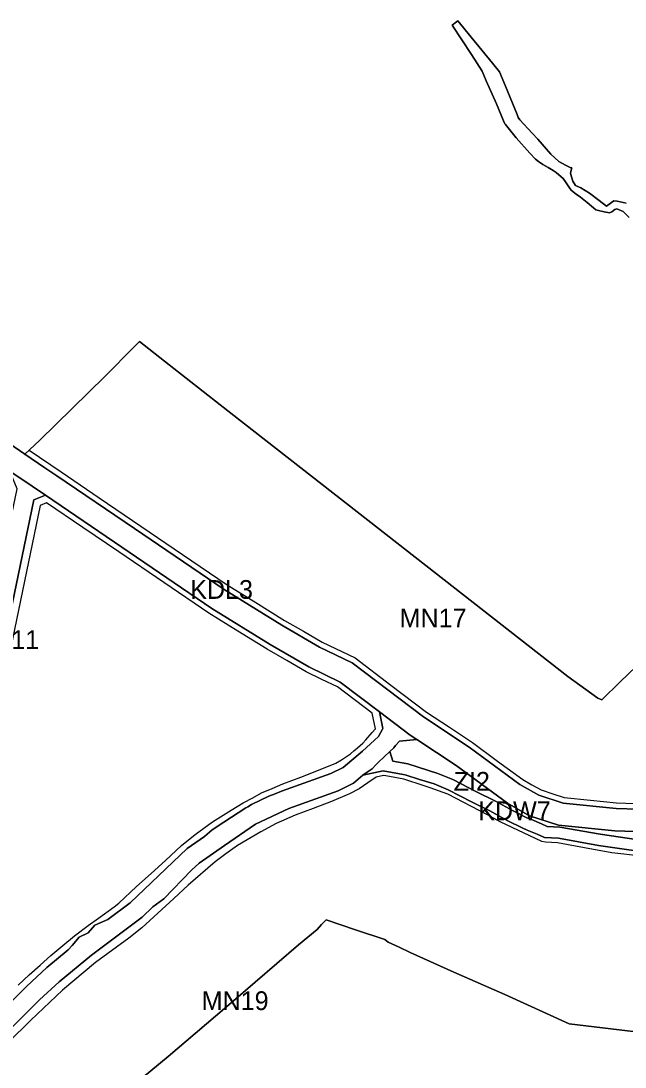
# Model space of a CAD drawing. Extents: x 7439486 to 7443435, y 5551288 to 5554556.
# Drawn here: x 7440135 to 7440457, y 5552234 to 5552792 of the extents above; entities that cross this region are included whole.
import ezdxf

# ---------------------------------------------------------------- set-up
doc = ezdxf.new("R2010")
doc.units = 0
for name, color, linetype in [('linie_rozgraniczajace', 7, 'Continuous'), ('linie_zabudowy_nieprzekraczalne', 7, 'Continuous'), ('oznaczenia_przeznaczen', 7, 'Continuous')]:
    doc.layers.add(name, color=color, linetype=linetype)

msp = doc.modelspace()

# ---------------------------------------------------------------- linework, layer by layer
at = {"layer": 'linie_rozgraniczajace'}
for points in [[(7440386.06, 5552769.12), (7440374.68, 5552782.97), (7440367.62, 5552791.7), (7440366.85, 5552791.14), (7440364.58, 5552789.48), (7440374.9, 5552773.74), (7440380.49, 5552764.99), (7440382.63, 5552759.83), (7440388.1, 5552747.54), (7440391.95, 5552738.4), (7440392.53, 5552736.87), (7440392.92, 5552736.39), (7440398.67, 5552729.4), (7440405.87, 5552721.22), (7440409, 5552718.06), (7440410.45, 5552716.72), (7440412.89, 5552715.23), (7440415.7, 5552713.63), (7440418.36, 5552711.92), (7440420.03, 5552710.9), (7440422.68, 5552708.6), (7440423.75, 5552707.64), (7440425.23, 5552705.4), (7440427.37, 5552702.17), (7440428.16, 5552701.36), (7440430.65, 5552699.38), (7440432.83, 5552697.75), (7440436.4, 5552694.9), (7440439.9, 5552691.96), (7440441.11, 5552690.9), (7440442.53, 5552690.55), (7440445.55, 5552689.95), (7440448.31, 5552689.31), (7440449.58, 5552689.87), (7440451.14, 5552691.2), (7440452.29, 5552691.54), (7440455.74, 5552690.05), (7440458.77, 5552686.94)], [(7440364.58, 5552789.48), (7440366.85, 5552791.14), (7440367.62, 5552791.7), (7440374.68, 5552782.97), (7440386.06, 5552769.12), (7440389.8, 5552764.58), (7440392.87, 5552756.99), (7440399.12, 5552741.74), (7440399.72, 5552740.28), (7440400.59, 5552739.04), (7440407.23, 5552731.85), (7440410.22, 5552728.6), (7440417.08, 5552720.61), (7440421.36, 5552716.67), (7440424.86, 5552714.85), (7440427.48, 5552713.63), (7440428.3, 5552713.45), (7440427.83, 5552711.36), (7440427.59, 5552710.27), (7440428.9, 5552706.33), (7440430.33, 5552703.92), (7440433.17, 5552702.62), (7440437.71, 5552699.92), (7440442.95, 5552695.9), (7440446.75, 5552692.98), (7440449.45, 5552694.93), (7440450.7, 5552695.83), (7440452.39, 5552695.59), (7440457.3, 5552694.53)], [(7440458.77, 5552686.94), (7440455.74, 5552690.05), (7440452.29, 5552691.54), (7440451.14, 5552691.2), (7440449.58, 5552689.87), (7440448.31, 5552689.31), (7440445.55, 5552689.95), (7440442.53, 5552690.55), (7440441.11, 5552690.9), (7440439.9, 5552691.96), (7440436.4, 5552694.9), (7440432.83, 5552697.75), (7440430.65, 5552699.38), (7440428.16, 5552701.36), (7440427.37, 5552702.17), (7440425.23, 5552705.4), (7440423.75, 5552707.64), (7440422.68, 5552708.6), (7440420.03, 5552710.9), (7440418.36, 5552711.92), (7440415.7, 5552713.63), (7440412.89, 5552715.23), (7440410.45, 5552716.72), (7440409, 5552718.06), (7440405.87, 5552721.22), (7440398.67, 5552729.4), (7440392.92, 5552736.39), (7440392.53, 5552736.87), (7440391.95, 5552738.4), (7440388.1, 5552747.54), (7440382.63, 5552759.83), (7440380.49, 5552764.99), (7440374.9, 5552773.74), (7440364.58, 5552789.48)], [(7440457.3, 5552694.53), (7440452.39, 5552695.59), (7440450.7, 5552695.83), (7440449.45, 5552694.93), (7440446.75, 5552692.98), (7440442.95, 5552695.9), (7440437.71, 5552699.92), (7440433.17, 5552702.62), (7440430.33, 5552703.92), (7440428.9, 5552706.33), (7440427.59, 5552710.27), (7440427.83, 5552711.36), (7440428.3, 5552713.45), (7440427.48, 5552713.63), (7440424.86, 5552714.85), (7440421.36, 5552716.67), (7440417.08, 5552720.61), (7440410.22, 5552728.6), (7440407.23, 5552731.85), (7440400.59, 5552739.04), (7440399.72, 5552740.28), (7440399.12, 5552741.74), (7440392.87, 5552756.99), (7440389.8, 5552764.58), (7440386.06, 5552769.12)], [(7440471.3, 5552455.81), (7440453.98, 5552439.3), (7440444.25, 5552429.76), (7440442.2, 5552430.66), (7440426.16, 5552442.24), (7440319.61, 5552525.55), (7440240.93, 5552587.09), (7440213.65, 5552608.41), (7440197.79, 5552620.8), (7440194.99, 5552617.95), (7440179.63, 5552602.3), (7440144.57, 5552567.93), (7440136.75, 5552560.73), (7440121.83, 5552570.88)], [(7440486.55, 5552370.64), (7440451.96, 5552371.77), (7440423.67, 5552374.68), (7440410.68, 5552378.91), (7440400.54, 5552384.66), (7440373.57, 5552404.53), (7440349.16, 5552420.72), (7440311.18, 5552449.5), (7440293.79, 5552457.89), (7440273.66, 5552469.52), (7440242.92, 5552488.57), (7440195.22, 5552521), (7440153.74, 5552549.19), (7440147.4, 5552553.5), (7440136.75, 5552560.73), (7440144.57, 5552567.93), (7440179.63, 5552602.3), (7440194.99, 5552617.95), (7440197.79, 5552620.8), (7440213.65, 5552608.41), (7440240.93, 5552587.09), (7440319.61, 5552525.55), (7440426.16, 5552442.24), (7440442.2, 5552430.66), (7440444.25, 5552429.76), (7440453.98, 5552439.3), (7440471.3, 5552455.81)], [(7440121.83, 5552570.88), (7440136.75, 5552560.73), (7440147.4, 5552553.5), (7440153.74, 5552549.19), (7440195.22, 5552521), (7440242.92, 5552488.57), (7440273.66, 5552469.52), (7440293.79, 5552457.89), (7440311.18, 5552449.5), (7440349.16, 5552420.72), (7440373.57, 5552404.53), (7440400.54, 5552384.66), (7440410.68, 5552378.91), (7440423.67, 5552374.68), (7440451.96, 5552371.77), (7440486.55, 5552370.64)], [(7440472.39, 5552359.1), (7440451.15, 5552359.79), (7440421.17, 5552362.88), (7440405.82, 5552367.87), (7440393.99, 5552374.57), (7440366.69, 5552394.7), (7440345.68, 5552408.63), (7440342.21, 5552410.93), (7440325.84, 5552423.34), (7440304.89, 5552439.21), (7440288.18, 5552447.28), (7440267.49, 5552459.22), (7440236.39, 5552478.5), (7440188.47, 5552511.07), (7440147.73, 5552538.77), (7440140.66, 5552543.57), (7440128.82, 5552551.62)], [(7440116.42, 5552416.13), (7440141.53, 5552536.28), (7440147.73, 5552538.77), (7440188.47, 5552511.07), (7440236.39, 5552478.5), (7440267.49, 5552459.22), (7440288.18, 5552447.28), (7440304.89, 5552439.21), (7440325.84, 5552423.34), (7440327.64, 5552414.48), (7440327.39, 5552414.03), (7440325.24, 5552410.26), (7440316.76, 5552402.3), (7440306.34, 5552393.71), (7440299.88, 5552390.44), (7440273.56, 5552381.11), (7440270.26, 5552379.55), (7440266.72, 5552378.42), (7440257.6, 5552373.91), (7440255.67, 5552372.69), (7440254.59, 5552372.12), (7440242.85, 5552364.45), (7440236.59, 5552360.37), (7440232.52, 5552356.88), (7440223.27, 5552350.49), (7440192.8, 5552321.47), (7440181.01, 5552312.64), (7440174.02, 5552309.54), (7440170.51, 5552305.56), (7440165.73, 5552303.17), (7440161.89, 5552298.74), (7440159.84, 5552296.36), (7440148.41, 5552286.98), (7440137.55, 5552276.9), (7440103.24, 5552242.87)], [(7440103.24, 5552242.87), (7440137.55, 5552276.9), (7440148.41, 5552286.98), (7440159.84, 5552296.36), (7440161.89, 5552298.74), (7440165.73, 5552303.17), (7440170.51, 5552305.56), (7440174.02, 5552309.54), (7440181.01, 5552312.64), (7440192.8, 5552321.47), (7440223.27, 5552350.49), (7440232.52, 5552356.88), (7440236.59, 5552360.37), (7440242.85, 5552364.45), (7440254.59, 5552372.12), (7440255.67, 5552372.69), (7440257.6, 5552373.91), (7440266.72, 5552378.42), (7440270.26, 5552379.55), (7440273.56, 5552381.11), (7440299.88, 5552390.44), (7440306.34, 5552393.71), (7440316.76, 5552402.3), (7440325.24, 5552410.26), (7440327.39, 5552414.03), (7440327.64, 5552414.48), (7440325.84, 5552423.34), (7440342.21, 5552410.93), (7440345.68, 5552408.63), (7440336.5, 5552407.72), (7440334.24, 5552405.46), (7440333.36, 5552404.17), (7440331.35, 5552402.26), (7440325.33, 5552396.54), (7440323.89, 5552395.1), (7440321.8, 5552393.01), (7440318.6, 5552390.84), (7440316.94, 5552389.48), (7440311.85, 5552385.29), (7440303.82, 5552381.23), (7440277.38, 5552371.86), (7440259.6, 5552363.44), (7440243.13, 5552352.05), (7440229.59, 5552342.71), (7440225.64, 5552338.94), (7440210.78, 5552323.7), (7440205.05, 5552319.33), (7440199.27, 5552313.82), (7440172.21, 5552293.57), (7440154.99, 5552279.44), (7440144.47, 5552269.69), (7440110.01, 5552235.5)], [(7440463.8, 5552355.09), (7440443.41, 5552358.06), (7440421.92, 5552361.85), (7440415.19, 5552362.24), (7440412.12, 5552363.55), (7440406.79, 5552365.84), (7440404.38, 5552366.87), (7440397.02, 5552370.55), (7440387.32, 5552375.85), (7440377.45, 5552380.75), (7440364.84, 5552387.25), (7440356.91, 5552390.49), (7440340.9, 5552395.6), (7440332.93, 5552397.06), (7440331.35, 5552402.26), (7440333.36, 5552404.17), (7440334.24, 5552405.46), (7440336.5, 5552407.72), (7440345.68, 5552408.63), (7440366.69, 5552394.7), (7440393.99, 5552374.57), (7440405.82, 5552367.87), (7440421.17, 5552362.88), (7440451.15, 5552359.79), (7440472.39, 5552359.1)], [(7440465.1, 5552348.83), (7440453.78, 5552350.49), (7440442.46, 5552352.14), (7440431.84, 5552354.01), (7440421.22, 5552355.88), (7440417.51, 5552356.1), (7440413.8, 5552356.31), (7440409.76, 5552358.04), (7440404.43, 5552360.32), (7440401.85, 5552361.43), (7440394.24, 5552365.23), (7440384.55, 5552370.53), (7440374.74, 5552375.39), (7440362.32, 5552381.79), (7440358.59, 5552383.32), (7440354.86, 5552384.85), (7440347.15, 5552387.31), (7440339.44, 5552389.77), (7440330.62, 5552391.39), (7440327.77, 5552391.91), (7440316.94, 5552389.48), (7440318.6, 5552390.84), (7440321.8, 5552393.01), (7440323.89, 5552395.1), (7440325.33, 5552396.54), (7440331.35, 5552402.26), (7440332.93, 5552397.06), (7440340.9, 5552395.6), (7440356.91, 5552390.49), (7440364.84, 5552387.25), (7440377.45, 5552380.75), (7440387.32, 5552375.85), (7440397.02, 5552370.55), (7440404.38, 5552366.87), (7440406.79, 5552365.84), (7440412.12, 5552363.55), (7440415.19, 5552362.24), (7440421.92, 5552361.85), (7440443.41, 5552358.06), (7440463.8, 5552355.09)], [(7440110.01, 5552235.5), (7440144.47, 5552269.69), (7440154.99, 5552279.44), (7440172.21, 5552293.57), (7440199.27, 5552313.82), (7440205.05, 5552319.33), (7440210.78, 5552323.7), (7440225.64, 5552338.94), (7440229.59, 5552342.71), (7440243.13, 5552352.05), (7440259.6, 5552363.44), (7440277.38, 5552371.86), (7440303.82, 5552381.23), (7440311.85, 5552385.29), (7440316.94, 5552389.48), (7440327.77, 5552391.91), (7440330.62, 5552391.39), (7440339.44, 5552389.77), (7440347.15, 5552387.31), (7440354.86, 5552384.85), (7440358.59, 5552383.32), (7440362.32, 5552381.79), (7440374.74, 5552375.39), (7440384.55, 5552370.53), (7440394.24, 5552365.23), (7440401.85, 5552361.43), (7440404.43, 5552360.32), (7440409.76, 5552358.04), (7440413.8, 5552356.31), (7440417.51, 5552356.1), (7440421.22, 5552355.88), (7440431.84, 5552354.01), (7440442.46, 5552352.14), (7440453.78, 5552350.49), (7440465.1, 5552348.83)], [(7440180.28, 5552212.35), (7440213.17, 5552239.53), (7440247.93, 5552269.3), (7440282.69, 5552299.06), (7440287.62, 5552303.2), (7440292.54, 5552307.34), (7440294.92, 5552309.86), (7440297.3, 5552312.37), (7440312.93, 5552307.16), (7440328.56, 5552301.94), (7440330.39, 5552300.59), (7440336.28, 5552297.77), (7440342.17, 5552294.96), (7440365.4, 5552284.51), (7440392.5, 5552272.64), (7440426.81, 5552256.92), (7440492.04, 5552249.24)], [(7440492.04, 5552249.24), (7440426.81, 5552256.92), (7440392.5, 5552272.64), (7440365.4, 5552284.51), (7440342.17, 5552294.96), (7440336.28, 5552297.77), (7440330.39, 5552300.59), (7440328.56, 5552301.94), (7440312.93, 5552307.16), (7440297.3, 5552312.37), (7440294.92, 5552309.86), (7440292.54, 5552307.34), (7440287.62, 5552303.2), (7440282.69, 5552299.06), (7440247.93, 5552269.3), (7440213.17, 5552239.53), (7440180.28, 5552212.35)]]:
    msp.add_lwpolyline(points, dxfattribs=at)
msp.add_lwpolyline([(7440096.73, 5552395.22), (7440100.84, 5552414.91), (7440101.21, 5552415.17), (7440106.86, 5552419.23), (7440132.57, 5552542.31), (7440128.82, 5552551.62), (7440140.66, 5552543.57), (7440147.73, 5552538.77), (7440141.53, 5552536.28), (7440116.42, 5552416.13), (7440119.99, 5552408.76), (7440115.87, 5552389.07)], close=True, dxfattribs=at)
at = {"layer": 'linie_zabudowy_nieprzekraczalne'}
for points in [[(7440139.08, 5552562.88), (7440156.04, 5552551.31), (7440176.45, 5552537.37), (7440220.73, 5552507.28), (7440244.56, 5552491.08), (7440259.88, 5552481.59), (7440275.2, 5552472.1), (7440285.2, 5552466.32), (7440295.2, 5552460.54), (7440312.76, 5552452.07), (7440331.82, 5552437.62), (7440350.89, 5552423.17), (7440363.09, 5552415.08), (7440375.29, 5552406.99), (7440388.73, 5552397.08), (7440402.17, 5552387.18), (7440407.03, 5552384.42), (7440411.9, 5552381.67), (7440418.09, 5552379.65), (7440424.29, 5552377.64), (7440438.23, 5552376.2), (7440452.16, 5552374.77), (7440486.5, 5552373.64)], [(7440133.19, 5552277.51), (7440139.03, 5552283.16), (7440144.85, 5552288.26), (7440150.67, 5552293.36), (7440157.06, 5552298.67), (7440163.27, 5552303.83), (7440170.58, 5552309.34), (7440176.08, 5552313.3), (7440184.3, 5552319.38), (7440186.82, 5552321.29), (7440196.34, 5552330.18), (7440204.07, 5552337.2), (7440211.65, 5552344.09), (7440220.24, 5552352.04), (7440227.52, 5552357.9), (7440236.85, 5552364.62), (7440246.75, 5552370.93), (7440253.19, 5552374.79), (7440258.21, 5552377.52), (7440262.89, 5552380.07), (7440268.53, 5552382.47), (7440274.18, 5552384.87), (7440283.87, 5552388.56), (7440293.29, 5552392.15), (7440302.48, 5552395.99), (7440305.53, 5552397.73), (7440310.29, 5552400.94), (7440312.13, 5552402.5), (7440313.98, 5552404.05), (7440316.86, 5552406.61), (7440318.48, 5552408.43), (7440321.85, 5552412.26), (7440323.6, 5552414.28), (7440321.92, 5552422.54), (7440303.32, 5552436.64), (7440295.04, 5552440.63), (7440286.77, 5552444.62), (7440276.36, 5552450.64), (7440265.95, 5552456.65), (7440250.35, 5552466.32), (7440234.75, 5552475.98), (7440210.77, 5552492.29), (7440186.78, 5552508.59), (7440167.57, 5552521.65), (7440148.36, 5552534.71), (7440145, 5552533.36), (7440120.61, 5552416.65)], [(7440465.41, 5552346.3), (7440449.58, 5552348.23), (7440435.09, 5552350.84), (7440420.59, 5552353.45), (7440414.18, 5552353.78), (7440412.25, 5552354.25), (7440390.15, 5552364.71), (7440383.35, 5552368.34), (7440362.2, 5552379.42), (7440352.75, 5552382.86), (7440349.63, 5552383.87), (7440338.79, 5552387.4), (7440329.1, 5552389.13), (7440327.97, 5552389.4), (7440324.06, 5552388.52), (7440319.49, 5552385.44), (7440314.92, 5552382.35), (7440309.87, 5552379.57), (7440300.24, 5552375.54), (7440290.44, 5552371.81), (7440280.91, 5552368.17), (7440270.72, 5552363.84), (7440262.45, 5552359.35), (7440250.14, 5552351.98), (7440243.89, 5552347.56), (7440238.11, 5552343.35), (7440223.81, 5552330.82), (7440216.17, 5552323.88), (7440199.11, 5552308.14), (7440192.2, 5552302.73), (7440174.44, 5552289.72), (7440156.88, 5552274.87), (7440139.93, 5552258.97), (7440115.61, 5552235.05)]]:
    msp.add_lwpolyline(points, dxfattribs=at)

# ---------------------------------------------------------------- texts
at = {"layer": 'oznaczenia_przeznaczen'}
for s, p in [('KDL3', (7440224.89, 5552483.57)), ('MN17', (7440336.49, 5552468.31)), ('KDD11', (7440101.28, 5552456.81)), ('ZI2', (7440365.32, 5552381.27)), ('KDW7', (7440378.4, 5552365.55)), ('MN19', (7440231, 5552264.3))]:
    msp.add_text(s, height=10, dxfattribs=at).set_placement(p)

doc.saveas('drawing.dxf')
